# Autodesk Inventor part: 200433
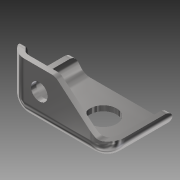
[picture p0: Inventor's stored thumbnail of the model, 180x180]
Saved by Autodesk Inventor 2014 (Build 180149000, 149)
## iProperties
Created: 2007-12
Part Number: 200433
Document SubType Name: Modeling
Designer: MM
Density: 7.85 g/cm^3
Mass: 44.1035 g
Surface Area: 50.9461 cm^2
Volume: 5.61828 cm^3
Material: Steel
Description: CORNER BRACKET
Appearance: Steel - Polished
Component Category: Lower Component
Author: MM
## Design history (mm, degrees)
node "201054" dims "d0" = 10
body "Solid1"
tag "TaggingFeature2"
feature "DerivedBody::D-201054" dims "d0" = 10
